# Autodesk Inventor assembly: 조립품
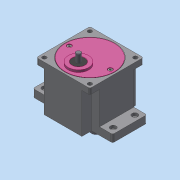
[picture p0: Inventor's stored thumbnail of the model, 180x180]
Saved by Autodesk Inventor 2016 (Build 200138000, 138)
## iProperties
Created: 2020-08
Part Number: 조립품
Material: 일반
Document SubType Name: Assembly
Designer: User
Author: User
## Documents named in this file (10)
- C:\Users\User\Desktop\700815V1009\조립품.iam
- C:\Users\User\Desktop\700815V1009\메인 축.ipt
- C:\Users\User\Desktop\700815V1009\베어링 608.ipt
- C:\Users\User\Desktop\700815V1009\베어링 6003.ipt
- C:\Users\User\Desktop\700815V1009\본체.ipt
- C:\Users\User\Desktop\700815V1009\볼트 M4.ipt
- C:\Users\User\Desktop\700815V1009\서브 축.ipt
- C:\Users\User\Desktop\700815V1009\오일 실 8 22 7.ipt
- C:\Users\User\Desktop\700815V1009\오일 실 17 32 8.ipt
- C:\Users\User\Desktop\700815V1009\커버.ipt
